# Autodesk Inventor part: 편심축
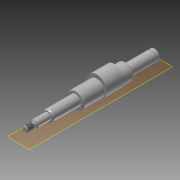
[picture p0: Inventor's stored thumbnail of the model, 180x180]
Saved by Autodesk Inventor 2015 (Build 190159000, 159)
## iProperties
Created: 2015-09
Part Number: 편심축
Material: 강철, 연강
Document SubType Name: Modeling
Designer: mduedu
Density: 1 g/cm^3
Appearance: 강철
Author: mduedu
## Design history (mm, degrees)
sketch "스케치1"
  geometry: L1 (-91, 0)-(91, 0); L2 (-91, 0)-(-91, 7.5); L3 (-91, 7.5)-(-49.85, 7.5); L4 (-49.85, 7.5)-(-49.85, 11.5); L5 (-49.85, 11.5)-(20.15, 11.5); L6 (20.15, 11.5)-(20.15, 7.5); L7 (20.15, 7.5)-(59.15, 7.5); L8 (59.15, 7.5)-(59.15, 5); L9 (59.15, 5)-(78.15, 5); L10 (78.15, 5)-(78.15, 3); L11 (78.15, 3)-(80.15, 3); L12 (81.882, 4)-(91, 4); L13 (91, 4)-(91, 0); L14 (80.15, 3)-(81.882, 4); 2 further points
  constraints: 28 end point, 9 parallel, 2 perpendicular, 1 coincident, 1 collinear, 1 horizontal, 1 midpoint
  dimensions: "d0" = 41.15 distance of L2.end L3.end; "d2" = 70 distance of L4.end L5.end; "d3" = 39 distance of L6.end L7.end; "d4" = 182 distance of L1.start L1.end; "d5" = 19 distance of L8.end L9.end; "d7" = 8 diameter of L12 L1; "d8" = 6 diameter of L11 L1; "d9" = 10 diameter of L9 L1; "d10" = 15 diameter of L7 L1; "d11" = 23 diameter of L5 L1; "d12" = 15 diameter of L3 L1; "d40" = 30 deg angle of L14 L12; "d41" = 2 distance of L10.end L11.end; "d42" = 3.73205 horizontal distance of L12.start L10.end (derived)
revolve "회전1" sketch "스케치1" stored, may be unused: angle "d13" = 90 deg
fillet "모깎기1" dims "d43" = 0.6
sketch "스케치2"
  geometry: L1 (-91, 7.5)-(-49.85, 7.5) reference; L2 (-91, -7.5)-(-91, 7.5) reference; L3 (91, -4)-(91, 4) reference; L4 (-91, 0)-(91, 0); L5 (-86, 7.5)-(-84.85, 7.5); L6 (-84.85, 7.5)-(-84.85, 7.15); L7 (-84.85, 7.15)-(-86, 7.15); L8 (-86, 7.15)-(-86, 7.5); 1 further point
  constraints: 10 end point, 2 midpoint, 2 parallel, 1 horizontal, 1 perpendicular, 1 point on line
  dimensions: "d14" = 5 distance between parallel lines of L8 L2; "d15" = 14.3 diameter of L7 L4; "d16" = 1.15 distance of L6.end L7.end
revolve "회전2" sketch "스케치2" stored, may be unused: angle "d17" = 90 deg
node "작업 평면1"
sketch "스케치3"
  geometry: C1 r 11.5 at (0, 0) reference; C2 r 14 at (0, 2.5); 1 further point
  constraints: 1 centre point, 1 tangent, 1 vertical alignment
  dimensions: "d19" = 28 diameter of C2
extrude "돌출1" join sketch "스케치3" distance "d21" = 25; taper "d22" = 0 deg
node "작업 평면2"
sketch "스케치4"
  geometry: L1 (9.5, 7.5)-(9.5, -7.5) reference; L2 (-9.5, 5)-(-9.5, -5) reference; L3 (9.5, 0)-(-9.5, 0); L4 (-5, -1.5)-(4, -1.5); L5 (4, 1.5)-(-5, 1.5); A1 r 1.5 centre (4, 0) between (4, -1.5) and (4, 1.5); A2 r 1.5 centre (-5, 0) between (-5, 1.5) and (-5, -1.5); 1 further point
  constraints: 6 end point, 4 point on circle, 4 tangent, 2 centre point, 2 midpoint, 2 parallel, 1 point on line
  dimensions: "d23" = 3 distance between parallel lines of L5 L4; "d25" = 12 dimension on A2 A1; "d26" = 3 distance edge to line of A2 L2
extrude "돌출2" cut sketch "스케치4" distance "d27" = 1.8; taper "d28" = 0 deg
chamfer "모따기1" distance "d29" = 1; stored, may be unused: second distance "d30" = 2, angle "d31" = 45 deg
sketch "스케치5"
  geometry: L1 (80.289, 3.08)-(81.882, 4) reference; L2 (81.882, 4)-(91, 4) reference; L3 (91, 4)-(91, -4) reference; L4 (91, -4)-(81.882, -4) reference; L5 (81.882, -4)-(80.289, -3.08) reference; L6 (79.989, -3)-(78.75, -3) reference; L7 (78.15, -3.6)-(78.15, -5) reference; L8 (78.15, -5)-(75.15, -5) reference; L9 (75.15, -5)-(75.15, -3.2) reference; L10 (75.15, -3.2)-(63.15, -3.2) reference; L11 (63.15, -3.2)-(63.15, -5) reference; L12 (63.15, -5)-(59.15, -5) reference; L13 (59.15, -5)-(59.15, -7.5) reference; L14 (59.15, -7.5)-(20.15, -7.5) reference; L15 (20.15, -7.5)-(20.15, -10.5) reference; L16 (20.15, -10.5)-(19.15, -11.5) reference; L17 (19.15, -11.5)-(-9.35, -11.5) reference; L18 (-9.35, -11.5)-(-34.35, -11.5) reference; L19 (-34.35, -11.5)-(-48.85, -11.5) reference; L20 (-48.85, -11.5)-(-49.85, -10.5) reference; L21 (-49.85, -10.5)-(-49.85, -7.5) reference; L22 (-49.85, -7.5)-(-84.85, -7.5) reference; L23 (-84.85, -7.5)-(-84.85, -7.15) reference; L24 (-84.85, -7.15)-(-86, -7.15) reference; L25 (-86, -7.15)-(-86, -7.5) reference; L26 (-86, -7.5)-(-90, -7.5) reference; L27 (-90, -7.5)-(-91, -6.5) reference; L28 (-91, -6.5)-(-91, 6.5) reference; L29 (-91, 6.5)-(-90, 7.5) reference; L30 (-90, 7.5)-(-86, 7.5) reference; L31 (-86, 7.5)-(-86, 7.15) reference; L32 (-86, 7.15)-(-84.85, 7.15) reference; L33 (-84.85, 7.15)-(-84.85, 7.5) reference; L34 (-84.85, 7.5)-(-49.85, 7.5) reference; L35 (-49.85, 7.5)-(-49.85, 10.5) reference; L36 (-49.85, 10.5)-(-48.85, 11.5) reference; L37 (-48.85, 11.5)-(-34.35, 11.5) reference; L38 (-34.35, 11.5)-(-34.35, 16.5) reference; L39 (-34.35, 16.5)-(-9.35, 16.5) reference; L40 (-9.35, 16.5)-(-9.35, 11.5) reference; L41 (-9.35, 11.5)-(19.15, 11.5) reference; L42 (19.15, 11.5)-(20.15, 10.5) reference; L43 (20.15, 10.5)-(20.15, 7.5) reference; L44 (20.15, 7.5)-(59.15, 7.5) reference; L45 (59.15, 7.5)-(59.15, 5) reference; L46 (59.15, 5)-(78.15, 5) reference; L47 (78.15, 5)-(78.15, 3.6) reference; L48 (78.75, 3)-(79.989, 3) reference; L49 (0, 0)-(91, 0); L50 (59.15, -6.55)-(57.505, -7.5); L51 (57.505, -7.5)-(59.15, -7.5); L52 (59.15, -7.5)-(59.15, -6.55); A1 r 0.6 centre (79.989, 3.6) between (79.989, 3) and (80.289, 3.08) reference; A2 r 0.6 centre (79.989, -3.6) between (80.289, -3.08) and (79.989, -3) reference; A3 r 0.6 centre (78.75, -3.6) between (78.75, -3) and (78.15, -3.6) reference; A4 r 0.6 centre (78.75, 3.6) between (78.15, 3.6) and (78.75, 3) reference
  constraints: 8 end point, 2 point on line, 1 midpoint, 1 parallel, 1 perpendicular
  dimensions: "d44" = 30 deg angle of L50 L51; "d45" = 13.1 diameter of L50.start L49
revolve "회전3" sketch "스케치5" stored, may be unused: angle "d46" = 90 deg
fillet "모깎기2" dims "d47" = 4, "d48" = 0.5
feature "스레드1" dims "d32" = 10, "d33" = 0
chamfer "모따기2" distance "d34" = 1; stored, may be unused: second distance "d35" = 2, angle "d36" = 45 deg
chamfer "모따기3" distance "d37" = 1; stored, may be unused: second distance "d38" = 2, angle "d39" = 45 deg
node "작업 평면3"
node "솔리드1"
node "절단 모서리 투영1"
other parameters: "d18" = -29.5, "d49" = -12
